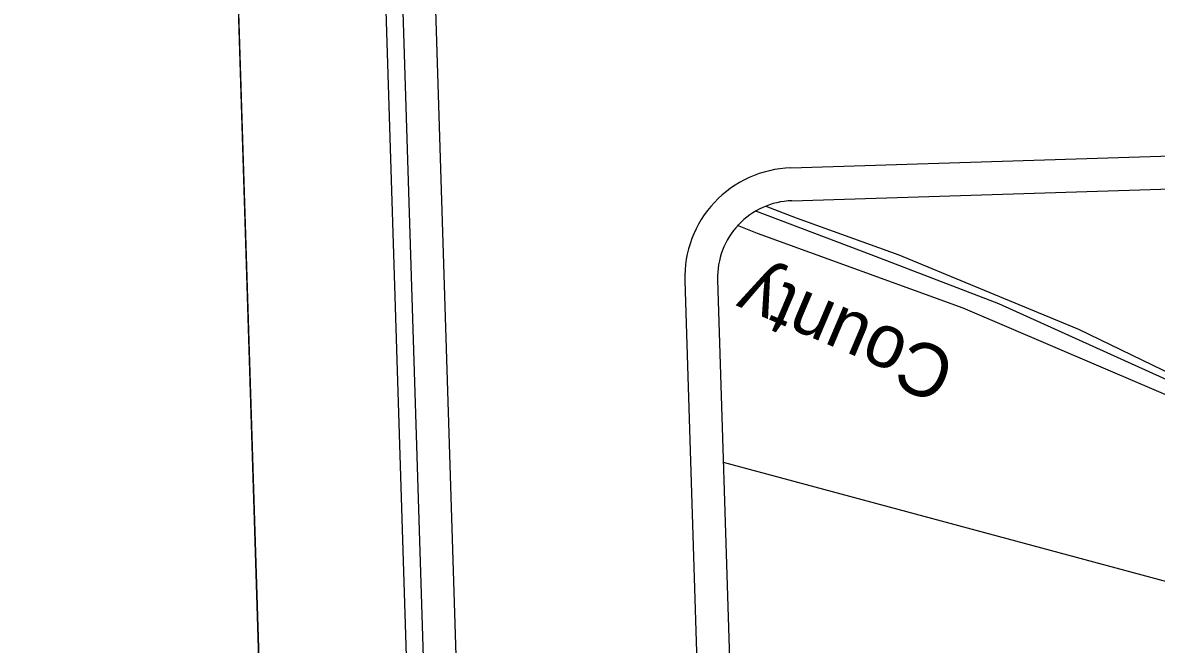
# Model space of a CAD drawing. Extents: x 2308163 to 2335412, y -96774 to 127732.
# Drawn here: x 2325774 to 2326033, y 123351.4 to 123493.3 of the extents above; entities that cross this region are included whole.
import ezdxf

# ---------------------------------------------------------------- set-up
doc = ezdxf.new("R2010")
doc.units = 0
for name, color, linetype in [('Old_Level_1', 7, 'Continuous'), ('Old_Level_19', 7, 'Continuous'), ('Old_Level_52', 7, 'Continuous'), ('Old_Level_60', 7, 'Continuous'), ('Old_Level_63', 7, 'Continuous'), ('Sheet Cutting Line CELL', 7, 'Continuous'), ('Sheet Plot Border Inside CELL', 7, 'Continuous'), ('Sheet Plot Border Outside CELL', 7, 'Continuous'), ('Sheet Title CELL', 7, 'Continuous')]:
    doc.layers.add(name, color=color, linetype=linetype)

msp = doc.modelspace()

# ---------------------------------------------------------------- linework, layer by layer
at = {"layer": 'Old_Level_1'}
for p, q in [((2325949.48, 123460.16), (2326443.34, 123475.72)), ((2325949.72, 123452.66), (2326443.57, 123468.22)), ((2325932.78, 123434.62), (2325949.42, 122906.55))]:
    msp.add_line(p, q, dxfattribs=at)
msp.add_lwpolyline([(2325925.28, 123434.38), (2325941.92, 122906.32)], dxfattribs=at)
for radius in [25, 17.5]:
    msp.add_arc((2325950.27, 123435.17), radius, 91.8048, 181.8048, dxfattribs=at)
at = {"layer": 'Old_Level_52'}
msp.add_lwpolyline([(2326352.46, 123278.37), (2326344.49, 123279.39), (2326334.11, 123277.47), (2326314.41, 123278.3), (2326300.12, 123278.02), (2326291.22, 123283.57), (2326287.11, 123292.06), (2326280.06, 123298.67), (2326266.15, 123306.08), (2326194.23, 123339.67), (2326117.56, 123374.58), (2325996.97, 123429.09), (2325967.84, 123440.3), (2325941.49, 123450.31)], dxfattribs=at)
at = {"layer": 'Old_Level_60'}
for points in [[(2325943.78, 123451.42), (2325950.75, 123448.77), (2325974.15, 123440.27), (2325991.46, 123433.15), (2326015.22, 123423.35), (2326044.14, 123409.29), (2326072.73, 123397.29), (2326127.66, 123373.96)], [(2325941.92, 123445.17), (2325937.35, 123446.97)], [(2326040.36, 123406.16), (2325988.84, 123428.14), (2325941.92, 123445.17)]]:
    msp.add_lwpolyline(points, dxfattribs=at)
at = {"layer": 'Old_Level_63'}
msp.add_lwpolyline([(2326475.8, 123239.36), (2326422.14, 123261.61), (2325934.09, 123392.92)], dxfattribs=at)
at = {"layer": 'Sheet Cutting Line CELL'}
msp.add_line((2325853.59, 122535.57), (2325774.04, 125060.32), dxfattribs=at)
at = {"layer": 'Sheet Plot Border Inside CELL'}
msp.add_lwpolyline([(2327468.5, 122605.97), (2327389.78, 125104.48), (2325807.91, 125054.63), (2325886.64, 122556.12)], close=True, dxfattribs=at)
at = {"layer": 'Sheet Plot Border Outside CELL'}
msp.add_lwpolyline([(2325774.04, 125060.32), (2325853.59, 122535.57), (2327502.76, 122587.54), (2327423.2, 125112.28)], close=True, dxfattribs=at)
at = {"layer": 'Sheet Title CELL'}
for points in [[(2325812.8, 125021.04), (2325882.7, 122802.1)], [(2325820.53, 125013.76), (2325887.61, 122884.84)]]:
    msp.add_lwpolyline(points, dxfattribs=at)

# ---------------------------------------------------------------- texts
at = {"layer": 'Old_Level_19'}
msp.add_text('County', height=12.145, rotation=156.9737, dxfattribs=at).set_placement((2325987.85, 123417.25))

doc.saveas('drawing.dxf')
